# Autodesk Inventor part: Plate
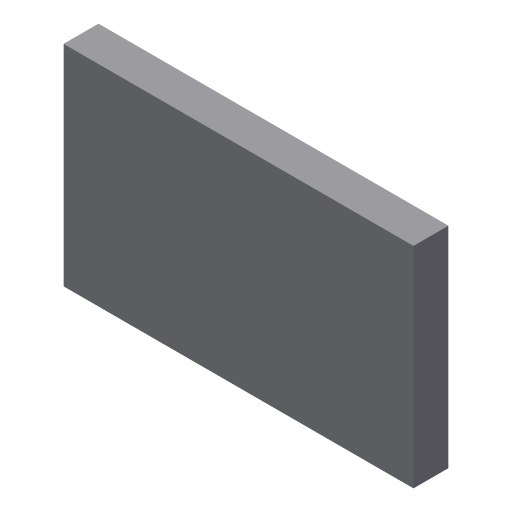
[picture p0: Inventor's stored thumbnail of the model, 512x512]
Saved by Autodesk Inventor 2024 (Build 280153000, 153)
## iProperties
Created: 2009-05
Part Number: Plate
Document SubType Name: Modeling
Designer: Sham
Density: 1 g/cm^3
Material: Generic
Appearance: Default
Author: Sham
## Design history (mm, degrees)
sketch "Sketch1"
  geometry: L1 (12.538, -14.287)-(-37.462, -14.288); L2 (-37.462, -14.288)-(-37.463, 15.712); L3 (-37.463, 15.712)-(12.537, 15.713); L4 (12.537, 15.713)-(12.538, -14.287)
  constraints: 8 end point, 2 parallel, 1 horizontal, 1 perpendicular
  dimensions: "d0" = 50 distance of L1.start L1.end; "d1" = 30 distance of L3.end L1.start
extrude "Extrusion1" new body sketch "Sketch1" distance "d2" = 5; taper "d3" = 0 deg
body "Solid1"
